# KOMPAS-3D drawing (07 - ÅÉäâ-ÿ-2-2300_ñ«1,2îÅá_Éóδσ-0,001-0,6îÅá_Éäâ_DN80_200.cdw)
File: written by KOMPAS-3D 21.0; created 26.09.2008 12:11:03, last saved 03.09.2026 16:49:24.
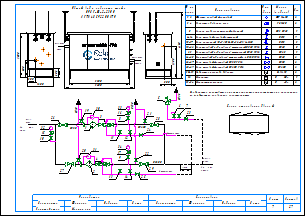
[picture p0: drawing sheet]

Sheets 1-2: A3, landscape

Document properties: Наименование: Макро:21; Автор: RaskoAdmin; Форматы листов документа: 2xA3; Полное имя файла: \\UR38nt01\Departments\КТО\КБ ПУРДГ\Заявки\Прайс-лист на типовые шкафы ГРПШ\ПРДГ_стандарт_20_03_2026\ПРДГ с РДГ(Н, В)\ПРДГ-Ш-2-2300_до1,2МПа_Рвых-0,001-0,6МПа_РДГ_DN80_200.cdw

Title block, sheet 1: Наименование: Пункт учета газа / ПУГ-Ш-400-Р / ЛГТИ.485922.001ТУ; designation: ЛГТИ.03.4411141; sheet number: 1; Количество листов документа: 2; organisation: ООО "ЭЛЬСТЕР Газэлектроника"; Форматы листов документа: A3; stored path: C:\Рабочие документы\Компас\ПУГ\Схема.cdw; Разработал: Устинов; Проверил: Кошкин; Утвердил: Кошкин
Title block, sheet 2: sheet number: 2; stored path: D:\Рабочие документы\Заявки\ПУРДГ\ПУРДГ-ШУЭО-2-100-Р 4411220.cdw; designation, second copy: ЛГТИ.03.4411141-

Views: Вид 1, Вид 2
Referenced files: wcvoit.frw
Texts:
  Normal
  № на
  схеме
  Усл.
  обозн.
  Марка
  (модель)
  Кол.
  Фильтр газовый фланцевый
  ФГ 16-80
  Регулятор давления газа
  РДГ-50
  Клапан предохранительный сбросной
  ПСК DN25
  Кран шаровой газовый латунный
  DN15
  Кран кнопочный VE-РАСКО-НЗ-1,6-G1/2-М20
  Кран шаровой "под приварку" штуцерный DN20 PN16
  Кран шаровой "под приварку" штуцерный DN25 PN16
  Кран шаровой "под приварку" штуцерный п/п DN20 PN16
  DN20
  DN25
  Кран шаровой фланцевый DN80 PN16
  Кран шаровой фланцевый DN200 PN16
  DN80
  DN200
  Индикатор перепада давления
  Delta 15
  Манометр
  Манометр-напоромер
  0...     МПа
  0...     кПа
  Общий вид и габариты шкафа
  ПРДГ-Ш-2-2300
  Выход газа
  Вход газа
  Схема открывания дверей
  logo-rasko-ge.png
  Предприятие изготовитель может заменять комплектующие на аналогичные,
  не ухудшающие заявленных характеристик.
  Вход
  газа
  PDI
  Выход
  Р=     кПа
  Импульс DN20
  ≥5DN
  HYSWLongFangSong
  Р=       МПа
  Должность
  Конструктор
  Фамилия
  Подпись
  Дата
  Согласовано
  Максимкин
  Лист
  Листов
  POLYLINE_STYLE_0.18_RGB_0_0_0
  POLYLINE_STYLE_0.50_RGB_0_0_0
  POLYLINE_STYLE_0.34_RGB_0_0_0
  PHANTOM_RGB_0_0_0_SC_1_THICK_0.18
  K5LT_THIN_RGB_0_0_0_THICK_0.18
  K5LT32769_RGB_0_0_0_THICK_0.18
  K5LT12_RGB_0_0_0_SC_1_THICK_0.18
  K5LT_DASHED_RGB_0_0_0_SC_1_THICK_0.18
  ACISOTGL_RGB_0_0_0_SC_0.8_THICK_0.25
  CONTINUOUS_RGB_0_127_31_THICK_0.3
  CONTINUOUS_RGB_0_0_255_THICK_0.35
  CONTINUOUS_RGB_255_0_0_THICK_0.35
  POLYLINE_STYLE_0.25_RGB_0_0_0
  CONTINUOUS_RGB_0_0_0_THICK_0.5
  POLYLINE_STYLE_0.35_RGB_0_0_255
  CONTINUOUS_RGB_0_0_0_THICK_0.4
  CONTINUOUS_RGB_0_0_0_THICK_0.35
  Без оформления
Dimensions and other numbers on the sheet: 1; 1, 2; 2; 3, 4; 5; 6-14; 9; 15-17; 3; 18-22; 23; 24-25; 26-27; 28-29; 30-31; 32; 33-34; 500; 1200; 305; 2000; 3600; 4130; 3300; 4; 10; 27; 28; 29; 8; 12; 19; 20; 21; 22; 25; 24; 30; 31; 15; 16; 26; 6; 7; 11; 14; 13; 33; 17; 34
